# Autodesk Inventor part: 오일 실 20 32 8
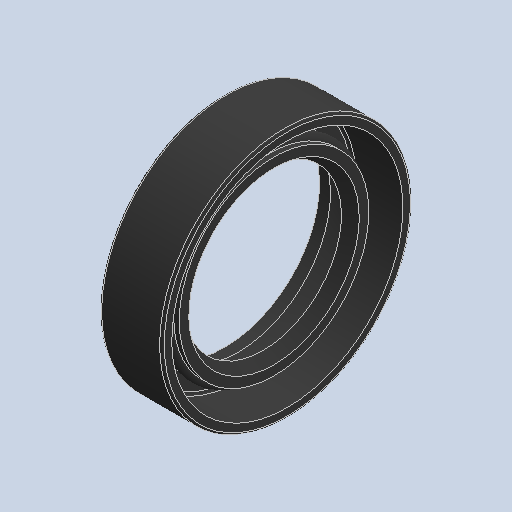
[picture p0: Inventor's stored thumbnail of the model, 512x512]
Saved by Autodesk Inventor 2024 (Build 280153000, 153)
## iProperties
Created: 2024-11
Part Number: 오일 실 20 32 8
Material: 고무
Description: 오일-실
Document SubType Name: Modeling
Designer: user
Density: 0.93 g/cm^3
Appearance: 기본값
Author: jhkim
Sending System: Autodesk Inventor 2025
Preprocessor: ST-DEVELOPER v20
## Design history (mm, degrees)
node "오일 실 20 32 81"
node "솔리드1"
body "Solid1"
